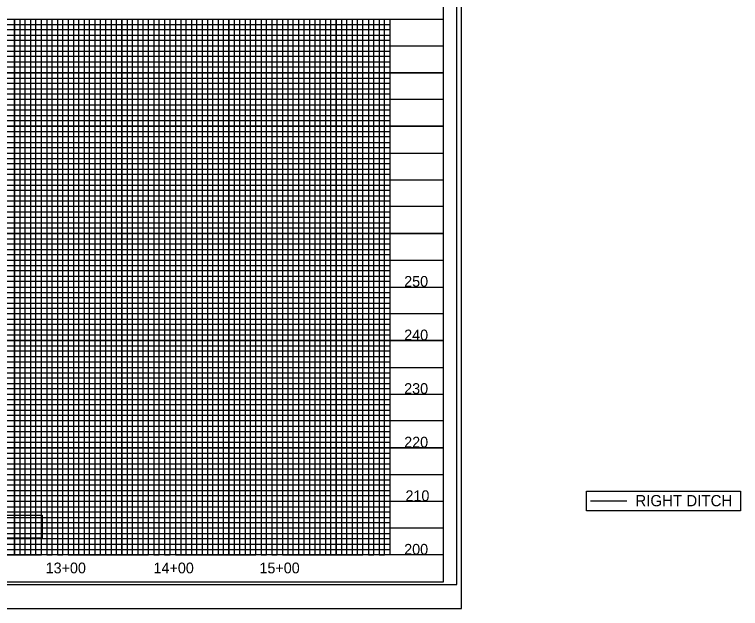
# Model space of a CAD drawing. Extents: x 1810963 to 1812960, y 722070 to 723170.
# Drawn here: x 1812230 to 1812908, y 722070 to 722624 of the extents above; entities that cross this region are included whole.
import ezdxf

# ---------------------------------------------------------------- set-up
doc = ezdxf.new("R2010")
doc.units = 0
for name, color, linetype in [('Exist Horizontal Alignment Tick Label', 7, 'Continuous'), ('Old_Level_11', 7, 'Continuous'), ('Old_Level_2', 7, 'Continuous'), ('Prop Conc 2ft 6in Curb and Gutter', 7, 'Continuous'), ('Prop RDY Traffic Signal CELL', 7, 'Continuous'), ('Prop Shade Heavy', 7, 'Continuous'), ('Prop Shade Light', 7, 'Continuous'), ('Prop Vertical Profile Ditch Grade Right', 7, 'Continuous'), ('Scratch_Level_0', 7, 'Continuous'), ('Sheet Block Title CELL', 7, 'Continuous'), ('Sheet Layout Profile Border Port 2', 7, 'Continuous'), ('Sheet North Arrow CELL', 7, 'Continuous'), ('Sheet Symbology CELL', 7, 'Continuous'), ('Sheet Title CELL', 7, 'Continuous')]:
    doc.layers.add(name, color=color, linetype=linetype)

msp = doc.modelspace()

# ---------------------------------------------------------------- linework, layer by layer
at = {"layer": 'Old_Level_11'}
msp.add_lwpolyline([(1810976.46, 722092.33), (1812642.96, 722092.33), (1812642.96, 723147.43), (1810976.46, 723147.43)], close=True, dxfattribs=at)
at = {"layer": 'Old_Level_2'}
for points in [[(1812763.88, 722179.51), (1812907.55, 722179.51), (1812907.55, 722161.02), (1812763.88, 722161.02)], [(1811991.02, 722156.96), (1812256.15, 722156.96), (1812256.15, 722135.44), (1811991.02, 722135.44)]]:
    msp.add_lwpolyline(points, close=True, dxfattribs=at)
at = {"layer": 'Prop Conc 2ft 6in Curb and Gutter'}
for p, q in [((1811130.46, 722619.88), (1812630.35, 722619.88)), ((1812230.46, 722619.88), (1812230.46, 722119.88)), ((1812280.46, 722619.88), (1812280.46, 722119.88)), ((1812330.46, 722619.88), (1812330.46, 722119.88)), ((1812380.46, 722619.88), (1812380.46, 722119.88)), ((1812430.46, 722619.88), (1812430.46, 722119.88)), ((1812480.46, 722619.88), (1812480.46, 722119.88)), ((1812530.46, 722619.88), (1812530.46, 722119.88)), ((1812580.46, 722619.88), (1812580.46, 722119.88)), ((1811130.46, 722569.88), (1812630.35, 722569.88)), ((1811130.46, 722519.88), (1812630.35, 722519.88)), ((1811130.46, 722469.88), (1812630.35, 722469.88)), ((1811130.46, 722419.88), (1812630.35, 722419.88)), ((1811130.46, 722369.88), (1812630.35, 722369.88)), ((1811130.46, 722319.88), (1812630.35, 722319.88)), ((1811130.46, 722269.88), (1812630.35, 722269.88)), ((1811130.46, 722219.88), (1812630.35, 722219.88)), ((1811130.46, 722169.88), (1812630.35, 722169.88))]:
    msp.add_line(p, q, dxfattribs=at)
at = {"layer": 'Prop RDY Traffic Signal CELL'}
msp.add_line((1810963.46, 722069.88), (1812647.46, 722069.88), dxfattribs=at)
at = {"layer": 'Prop Shade Heavy'}
for p, q in [((1812230.46, 722619.88), (1812280.46, 722619.88)), ((1812330.46, 722619.88), (1812380.46, 722619.88)), ((1812430.46, 722619.88), (1812480.46, 722619.88)), ((1812530.46, 722619.88), (1812580.46, 722619.88)), ((1812530.46, 722119.88), (1812530.46, 722119.88))]:
    msp.add_line(p, q, dxfattribs=at)
for points in [[(1812180.46, 722119.88), (1812230.46, 722119.88), (1812230.46, 722619.88), (1812280.46, 722619.88), (1812280.46, 722119.88), (1812330.46, 722119.88), (1812330.46, 722619.88), (1812380.46, 722619.88), (1812380.46, 722119.88), (1812430.46, 722119.88), (1812430.46, 722619.88), (1812480.46, 722619.88), (1812480.46, 722119.88), (1812530.46, 722119.88), (1812530.46, 722119.88), (1812530.46, 722619.88), (1812580.46, 722619.88), (1812580.46, 722119.88)], [(1812630.46, 722569.88), (1811130.46, 722569.88)], [(1812630.46, 722519.88), (1811130.46, 722519.88), (1811130.46, 722469.88), (1812630.46, 722469.88)], [(1812630.46, 722419.88), (1811130.46, 722419.88), (1811130.46, 722369.88), (1812630.46, 722369.88)], [(1812630.46, 722319.88), (1811130.46, 722319.88), (1811130.46, 722269.88), (1812630.46, 722269.88)], [(1812630.46, 722219.88), (1811130.46, 722219.88), (1811130.46, 722219.88), (1811130.46, 722169.88), (1812630.46, 722169.88)], [(1812630.46, 722119.88), (1811130.46, 722119.88)]]:
    msp.add_lwpolyline(points, dxfattribs=at)
at = {"layer": 'Prop Shade Light'}
for points in [[(1812205.46, 722119.88), (1812255.46, 722119.88), (1812255.46, 722619.88), (1812305.46, 722619.88), (1812305.46, 722119.88), (1812355.46, 722119.88), (1812355.46, 722619.88), (1812405.46, 722619.88), (1812405.46, 722119.88), (1812455.46, 722119.88), (1812455.46, 722619.88), (1812505.46, 722619.88), (1812505.46, 722119.88), (1812555.46, 722119.88), (1812555.46, 722619.88)], [(1811130.46, 722594.88), (1812630.46, 722594.88)], [(1812630.46, 722544.88), (1811130.46, 722544.88), (1811130.46, 722494.88), (1812630.46, 722494.88)], [(1812630.46, 722444.88), (1811130.46, 722444.88), (1811130.46, 722394.88), (1812630.46, 722394.88)], [(1812630.46, 722344.88), (1811130.46, 722344.88), (1811130.46, 722294.88), (1812630.46, 722294.88)], [(1812630.46, 722244.88), (1811130.46, 722244.88), (1811130.46, 722194.88), (1812630.46, 722194.88)], [(1812630.46, 722144.88), (1811130.46, 722144.88)]]:
    msp.add_lwpolyline(points, dxfattribs=at)
at = {"layer": 'Prop Vertical Profile Ditch Grade Right'}
msp.add_line((1812767.79, 722170.2), (1812801.44, 722170.2), dxfattribs=at)
at = {"layer": 'Sheet Layout Profile Border Port 2'}
msp.add_lwpolyline([(1811180.46, 722619.88), (1812580.46, 722619.88), (1812580.46, 722119.88), (1811180.46, 722119.88)], close=True, dxfattribs=at)
at = {"layer": 'Sheet North Arrow CELL'}
msp.add_lwpolyline([(1810963.46, 722069.88), (1812647.46, 722069.88), (1812647.46, 723169.88), (1810963.46, 723169.88)], close=True, dxfattribs=at)
at = {"layer": 'Sheet Symbology CELL'}
for p, q in [((1811130.46, 722619.88), (1812630.46, 722619.88)), ((1812630.46, 722119.88), (1811130.46, 722119.88)), ((1811130.46, 722094.88), (1812630.46, 722094.88))]:
    msp.add_line(p, q, dxfattribs=at)
msp.add_lwpolyline([(1812630.46, 723144.88), (1811130.46, 723144.88), (1811130.46, 722094.88), (1812630.46, 722094.88)], close=True, dxfattribs=at)
at = {"layer": 'Sheet Title CELL'}
for p, q in [((1811180.46, 722614.88), (1812580.46, 722614.88)), ((1812580.46, 722609.88), (1811180.46, 722609.88)), ((1811180.46, 722604.88), (1812580.46, 722604.88)), ((1812580.46, 722599.88), (1811180.46, 722599.88)), ((1811180.46, 722589.88), (1812580.46, 722589.88)), ((1812580.46, 722584.88), (1811180.46, 722584.88)), ((1811180.46, 722579.88), (1812580.46, 722579.88)), ((1812580.46, 722574.88), (1811180.46, 722574.88)), ((1811180.46, 722564.88), (1812580.46, 722564.88)), ((1812580.46, 722559.88), (1811180.46, 722559.88)), ((1811180.46, 722554.88), (1812580.46, 722554.88)), ((1812580.46, 722549.88), (1811180.46, 722549.88)), ((1811180.46, 722539.88), (1812580.46, 722539.88)), ((1812580.46, 722534.88), (1811180.46, 722534.88)), ((1811180.46, 722529.88), (1812580.46, 722529.88)), ((1812580.46, 722524.88), (1811180.46, 722524.88)), ((1811180.46, 722514.88), (1812580.46, 722514.88)), ((1812580.46, 722509.88), (1811180.46, 722509.88)), ((1811180.46, 722504.88), (1812580.46, 722504.88)), ((1812580.46, 722499.88), (1811180.46, 722499.88)), ((1811180.46, 722489.88), (1812580.46, 722489.88)), ((1812580.46, 722484.88), (1811180.46, 722484.88)), ((1811180.46, 722479.88), (1812580.46, 722479.88)), ((1812580.46, 722474.88), (1811180.46, 722474.88)), ((1811180.46, 722464.88), (1812580.46, 722464.88)), ((1812580.46, 722459.88), (1811180.46, 722459.88)), ((1811180.46, 722454.88), (1812580.46, 722454.88)), ((1812580.46, 722449.88), (1811180.46, 722449.88)), ((1811180.46, 722439.88), (1812580.46, 722439.88)), ((1812580.46, 722434.88), (1811180.46, 722434.88)), ((1811180.46, 722429.88), (1812580.46, 722429.88)), ((1812580.46, 722424.88), (1811180.46, 722425.03)), ((1811180.46, 722414.88), (1812580.46, 722414.88)), ((1812580.46, 722409.88), (1811180.46, 722409.88)), ((1811180.46, 722404.88), (1812580.46, 722404.88)), ((1812580.46, 722399.88), (1811180.46, 722399.88)), ((1811180.46, 722389.88), (1812580.46, 722389.88)), ((1812580.46, 722384.88), (1811180.46, 722384.88)), ((1811180.46, 722379.88), (1812580.46, 722379.88)), ((1812580.46, 722374.88), (1811180.46, 722374.88)), ((1811180.46, 722364.88), (1812580.46, 722364.88)), ((1812580.46, 722359.88), (1811180.46, 722359.88)), ((1811180.46, 722354.88), (1812580.46, 722354.88)), ((1812580.46, 722349.88), (1811180.46, 722349.88)), ((1811180.46, 722339.88), (1812580.46, 722339.88)), ((1812580.46, 722334.88), (1811180.46, 722334.88)), ((1811180.46, 722329.88), (1812580.46, 722329.88)), ((1812580.46, 722324.88), (1811180.46, 722324.88)), ((1811180.46, 722314.88), (1812580.46, 722314.88)), ((1812580.46, 722309.88), (1811180.46, 722309.88)), ((1811180.46, 722304.88), (1812580.46, 722304.88)), ((1812580.46, 722299.88), (1811180.46, 722299.88)), ((1811180.46, 722289.88), (1812580.46, 722289.88)), ((1812580.46, 722284.88), (1811180.46, 722284.88)), ((1811180.46, 722279.88), (1812580.46, 722279.88)), ((1812580.46, 722274.88), (1811180.46, 722274.88)), ((1811180.46, 722264.88), (1812580.46, 722264.88)), ((1812580.46, 722259.88), (1811180.46, 722259.88)), ((1811180.46, 722254.88), (1812580.46, 722254.88)), ((1812580.46, 722249.88), (1811180.46, 722249.88)), ((1811180.46, 722239.88), (1812580.46, 722239.88)), ((1812580.46, 722234.88), (1811180.46, 722234.88)), ((1811180.46, 722229.88), (1812580.46, 722229.88)), ((1812580.46, 722224.88), (1811180.46, 722224.88)), ((1811180.46, 722214.88), (1812580.46, 722214.88)), ((1812580.46, 722209.88), (1811180.46, 722209.88)), ((1811180.46, 722204.88), (1812580.46, 722204.88)), ((1812580.46, 722199.88), (1811180.46, 722199.88)), ((1811180.46, 722189.88), (1812580.46, 722189.88)), ((1812580.46, 722184.88), (1811180.46, 722184.88)), ((1811180.46, 722179.88), (1812580.46, 722179.88)), ((1812580.46, 722174.88), (1811180.46, 722174.88)), ((1811180.46, 722164.88), (1812580.46, 722164.88)), ((1812580.46, 722159.88), (1811180.46, 722159.88)), ((1811180.46, 722154.88), (1812580.46, 722154.88)), ((1812580.46, 722149.88), (1811180.46, 722149.88)), ((1811180.46, 722139.88), (1812580.46, 722139.88)), ((1812580.46, 722134.88), (1811180.46, 722134.88)), ((1811180.46, 722129.88), (1812580.46, 722129.88)), ((1811180.46, 722124.88), (1812580.46, 722124.88)), ((1812580.46, 722124.88), (1812580.46, 722124.88))]:
    msp.add_line(p, q, dxfattribs=at)
for points in [[(1812225.46, 722619.88), (1812235.46, 722619.88), (1812235.46, 722119.88), (1812240.46, 722119.88), (1812240.46, 722619.88), (1812245.46, 722619.88), (1812245.46, 722119.88), (1812250.46, 722119.88), (1812250.46, 722619.88), (1812260.46, 722619.88), (1812260.46, 722119.88), (1812265.46, 722119.88), (1812265.46, 722619.88), (1812270.46, 722619.88), (1812270.46, 722119.88), (1812275.46, 722119.88), (1812275.46, 722619.88), (1812285.46, 722619.88), (1812285.46, 722119.88), (1812290.46, 722119.88), (1812290.46, 722619.88), (1812295.46, 722619.88), (1812295.46, 722119.88), (1812300.46, 722119.88), (1812300.46, 722619.88), (1812310.46, 722619.88), (1812310.46, 722119.88), (1812315.46, 722119.88), (1812315.46, 722619.88), (1812320.46, 722619.88), (1812320.46, 722119.88)], [(1812320.46, 722119.88), (1812325.46, 722119.88), (1812325.46, 722619.88), (1812335.46, 722619.88), (1812335.46, 722119.88), (1812340.46, 722119.88), (1812340.46, 722619.88), (1812345.46, 722619.88), (1812345.46, 722119.88), (1812350.46, 722119.88), (1812350.46, 722619.88), (1812360.46, 722619.88), (1812360.46, 722119.88), (1812365.46, 722119.88), (1812365.46, 722619.88), (1812370.46, 722619.88), (1812370.46, 722119.88), (1812375.46, 722119.88), (1812375.46, 722619.88), (1812385.46, 722619.88), (1812385.46, 722119.88), (1812390.46, 722119.88), (1812390.46, 722619.88), (1812395.46, 722619.88), (1812395.46, 722119.88), (1812400.46, 722119.88), (1812400.46, 722619.88), (1812410.46, 722619.88), (1812410.46, 722119.88), (1812415.46, 722119.88), (1812415.46, 722619.88), (1812420.46, 722619.88), (1812420.46, 722119.88), (1812425.46, 722119.88), (1812425.46, 722619.88), (1812435.46, 722619.88), (1812435.46, 722119.88), (1812440.46, 722119.88), (1812440.46, 722619.88), (1812445.46, 722619.88), (1812445.46, 722119.88), (1812450.46, 722119.88), (1812450.46, 722619.88), (1812460.46, 722619.88), (1812460.46, 722119.88), (1812465.46, 722119.88), (1812465.46, 722619.88), (1812470.46, 722619.88), (1812470.46, 722119.88), (1812475.46, 722119.88), (1812475.46, 722619.88), (1812485.46, 722619.88), (1812485.46, 722119.88), (1812490.46, 722119.88), (1812490.46, 722619.88), (1812495.46, 722619.88), (1812495.46, 722119.88), (1812500.46, 722119.88), (1812500.46, 722619.88), (1812510.46, 722619.88), (1812510.46, 722119.88), (1812515.46, 722119.88), (1812515.46, 722619.88), (1812520.46, 722619.88), (1812520.46, 722119.88), (1812525.46, 722119.88), (1812525.46, 722619.88), (1812535.46, 722619.88), (1812535.46, 722119.88), (1812540.46, 722119.88), (1812540.46, 722619.88), (1812545.46, 722619.88), (1812545.46, 722119.88), (1812550.46, 722119.88), (1812550.46, 722619.88), (1812560.46, 722619.88), (1812560.46, 722119.88), (1812565.46, 722119.88), (1812565.46, 722619.88), (1812570.46, 722619.88), (1812570.46, 722119.88), (1812575.46, 722119.88), (1812575.46, 722619.88), (1812580.46, 722619.88)]]:
    msp.add_lwpolyline(points, dxfattribs=at)

# ---------------------------------------------------------------- texts
at = {"layer": 'Exist Horizontal Alignment Tick Label'}
msp.add_text('RIGHT DITCH', height=10.5, rotation=360, dxfattribs=at).set_placement((1812809.48, 722165.27))
at = {"layer": 'Scratch_Level_0'}
for s, p in [('250', (1812593.89, 722370.13)), ('240', (1812593.89, 722320.13)), ('230', (1812593.89, 722270.13)), ('220', (1812593.89, 722220.13)), ('210', (1812595.09, 722170.13)), ('200', (1812593.89, 722120.13))]:
    msp.add_text(s, height=10, dxfattribs=at).set_placement(p)
at = {"layer": 'Sheet Block Title CELL'}
for s, p in [('13+00', (1812259.46, 722102.7)), ('14+00', (1812360.1, 722102.7)), ('15+00', (1812458.88, 722102.7))]:
    msp.add_text(s, height=10, dxfattribs=at).set_placement(p)

doc.saveas('drawing.dxf')
